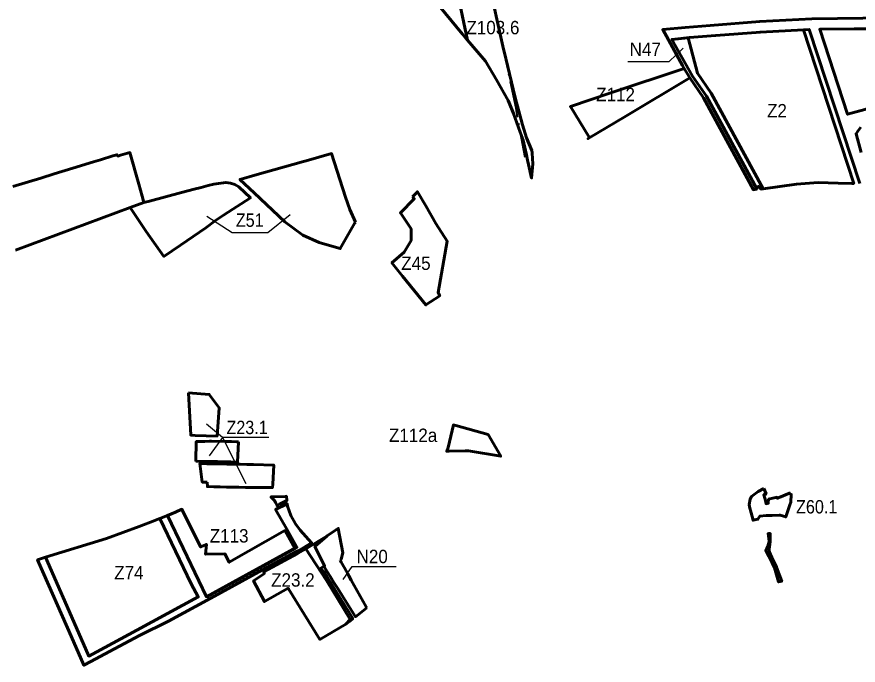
# Model space of a CAD drawing. Extents: x -650277 to -643420, y -1073980 to -1066720.
# Drawn here: x -648765 to -647259, y -1070690 to -1069529 of the extents above; entities that cross this region are included whole.
import ezdxf

# ---------------------------------------------------------------- set-up
doc = ezdxf.new("R2010")
doc.units = 0
doc.header["$LTSCALE"] = 9.6
doc.header["$PDMODE"] = 32
doc.header["$PDSIZE"] = 4.8
doc.linetypes.add('DOT_DASHED', pattern=[7.7, 5, -1.2, 0.3, -1.2])
for name, color, linetype, lineweight in [('1', 7, 'Continuous', 60), ('15', 7, 'Continuous', 60), ('17', 7, 'Continuous', 60), ('24', 7, 'Continuous', 60), ('3', 7, 'Continuous', 60), ('35', 7, 'Continuous', 60), ('36', 7, 'Continuous', 60), ('40', 7, 'Continuous', 60), ('42', 7, 'Continuous', 60), ('61', 7, 'Continuous', 60), ('62', 7, 'DOT_DASHED', 40), ('63', 7, 'Continuous', 25), ('7', 7, 'Continuous', 60), ('9', 7, 'Continuous', 60)]:
    doc.layers.add(name, color=color, linetype=linetype, lineweight=lineweight)

msp = doc.modelspace()

# ---------------------------------------------------------------- linework, layer by layer
at = {"layer": '1'}
for points in [[(-647356.899, -1069552.034), (-647433.779, -1069556.106), (-647433.779, -1069556.106), (-647513.66, -1069562.249), (-647514.067, -1069562.282), (-647560.836, -1069566.036), (-647563.104, -1069566.28)], [(-647369.3, -1069828.22), (-647330.46, -1069825.51), (-647294.38, -1069826.88), (-647270.09, -1069827.02), (-647266.581, -1069827.042), (-647356.899, -1069552.034)], [(-647563.104, -1069566.28), (-647546.777, -1069629.901), (-647521.943, -1069665.763)], [(-647521.943, -1069665.763), (-647428.993, -1069836.714), (-647369.3, -1069828.22)], [(-648368.25, -1070289.71), (-648372.1, -1070289.59), (-648380.97, -1070289.44), (-648392.94, -1070289.25), (-648416.93, -1070288.85), (-648420.39, -1070288.79), (-648428.98, -1070288.92), (-648435.93, -1070288.95), (-648444.15, -1070289.16), (-648444.85, -1070324.47)], [(-648444.85, -1070324.47), (-648444.85, -1070324.47), (-648430.02, -1070324.76), (-648418.1, -1070325), (-648406.09, -1070325.23), (-648394.08, -1070325.47), (-648382.06, -1070325.7), (-648370.07, -1070325.94), (-648368.25, -1070289.71)], [(-648307.13, -1070365.57), (-648305.47, -1070331.23), (-648341.46, -1070330.48), (-648353.32, -1070330.23), (-648365.35, -1070329.98), (-648389.43, -1070329.58), (-648401.41, -1070329.39), (-648413.45, -1070329.19), (-648425.43, -1070329), (-648437.65, -1070328.8), (-648433.46, -1070361.94), (-648424.31, -1070362.21)], [(-648424.31, -1070362.21), (-648424.05, -1070370), (-648412.75, -1070370.28), (-648401.35, -1070370.5), (-648390.06, -1070370.72), (-648378.73, -1070370.94), (-648367.67, -1070371.16), (-648355.67, -1070371.28), (-648343.67, -1070371.41), (-648331.67, -1070371.53), (-648319.67, -1070371.65), (-648307.67, -1070371.78), (-648307.13, -1070365.57)]]:
    msp.add_lwpolyline(points, dxfattribs=at)
for points in [[(-647251.002, -1069695.852), (-647219.628, -1069686.746), (-647203.374, -1069684.716), (-647139.649, -1069679.961), (-647113.255, -1069679.966), (-647082.761, -1069681.399), (-647083.356, -1069551.018), (-647140.247, -1069549.071), (-647158.572, -1069549.252), (-647211.05, -1069549.77), (-647227.623, -1069550.23), (-647327.682, -1069551.263), (-647277.71, -1069703.421)], [(-648458.28, -1070202.26), (-648454.038, -1070277.767), (-648446.18, -1070278.15), (-648406.8, -1070279.32), (-648403.04, -1070229.15), (-648420.7, -1070204.96)]]:
    msp.add_lwpolyline(points, close=True, dxfattribs=at)
at = {"layer": '15'}
for points in [[(-647204.293, -1069530.647), (-647341.697, -1069532.602), (-647434.969, -1069537.141), (-647523.931, -1069544.499), (-647568.792, -1069548.21), (-647608.81, -1069551.868), (-647598.735, -1069570.026), (-647573.15, -1069616.16), (-647570.37, -1069621.18), (-647560.36, -1069638.39), (-647535.588, -1069674.163), (-647446.322, -1069838.338), (-647441.19, -1069837.6), (-647440.46, -1069836.558), (-647530.471, -1069671.013), (-647555.266, -1069635.207), (-647592.199, -1069569.411), (-647560.836, -1069566.036), (-647514.067, -1069562.282), (-647513.66, -1069562.249), (-647433.779, -1069556.106), (-647433.779, -1069556.106), (-647356.899, -1069552.034), (-647346.554, -1069551.486), (-647256.034, -1069827.107)], [(-647256.061, -1069697.32), (-647277.71, -1069703.421), (-647327.682, -1069551.263), (-647204.208, -1069549.647)], [(-647253.45, -1069771.95), (-647262.46, -1069738.25), (-647259.11, -1069733.52), (-647253.97, -1069726.27)], [(-648213.87, -1070524.8), (-648221.359, -1070516.349), (-648215.48, -1070512.59), (-648214.34, -1070511.86), (-648231.53, -1070476.99), (-648210.48, -1070458.42), (-648247.67, -1070481.57), (-648211, -1070538)], [(-648176.54, -1070616.09), (-648169.28, -1070610.49), (-648163.8, -1070606.27), (-648213.87, -1070524.8)], [(-648211, -1070538), (-648168.575, -1070607.847), (-648176.54, -1070616.09)]]:
    msp.add_lwpolyline(points, dxfattribs=at)
for points in [[(-648303.705, -1070395.035), (-648302.028, -1070398.436), (-648299.32, -1070403.93), (-648295.18, -1070401.23), (-648281.907, -1070394.762), (-648282.582, -1070387.276), (-648284.37, -1070387.85), (-648310.275, -1070388.476)], [(-648550.72, -1070626.869), (-648636.757, -1070673.431), (-648655.178, -1070631.294), (-648714.161, -1070496.376), (-648728.255, -1070500.709), (-648725.835, -1070506.221), (-648668.207, -1070637.453), (-648645.331, -1070689.546), (-648632.652, -1070682.82), (-648599.66, -1070665.32), (-648545.76, -1070636.22), (-648494.04, -1070610.73), (-648417.855, -1070569.57), (-648325.21, -1070518.84), (-648264.56, -1070486.34), (-648260.57, -1070484.2), (-648237.475, -1070470.361), (-648257.96, -1070448.17), (-648266.416, -1070436.404), (-648274.808, -1070421.647), (-648280.974, -1070405.11), (-648281.388, -1070400.523), (-648302.01, -1070411.05), (-648282.01, -1070446.35), (-648263.859, -1070478.393), (-648425.835, -1070567.021), (-648439.409, -1070538.729), (-648495.666, -1070421.476), (-648509.227, -1070426.957), (-648452.97, -1070544.21), (-648440.531, -1070567.236)], [(-647404.96, -1070527.57), (-647401.35, -1070540.59), (-647395.75, -1070539.47), (-647404.879, -1070514.114), (-647413.552, -1070496.671), (-647417.297, -1070487.185), (-647418.038, -1070482.516), (-647417.482, -1070476.846), (-647416.37, -1070468.064), (-647416.148, -1070454.055), (-647418.49, -1070453.76), (-647420.13, -1070454.78), (-647420.22, -1070454.02), (-647418.41, -1070468.21), (-647420.74, -1070476.57), (-647422.285, -1070480.931), (-647424.226, -1070484.029), (-647422.19, -1070487.75), (-647414.6, -1070502.16), (-647410.86, -1070510.68), (-647408.82, -1070515.49)]]:
    msp.add_lwpolyline(points, close=True, dxfattribs=at)
msp.add_point((-648213.87, -1070524.8), dxfattribs=at)
at = {"layer": '17'}
msp.add_lwpolyline([(-647427.8, -1070373.32), (-647437.76, -1070378.66), (-647449.69, -1070387.83), (-647452.17, -1070392.38), (-647453.71, -1070401.81), (-647453.35, -1070406.09), (-647450.51, -1070416.96), (-647446.93, -1070429.99), (-647438.45, -1070428.47), (-647434.85, -1070422.64), (-647423.38, -1070421.87), (-647412.51, -1070421.5), (-647400.41, -1070421.08), (-647398.21, -1070421.15), (-647388.6, -1070424.24), (-647381.11, -1070402.45), (-647379.3, -1070397.57), (-647378.49, -1070383.91), (-647381.65, -1070381.45), (-647400.22, -1070389.64), (-647403.27, -1070390.91), (-647404, -1070388.84), (-647409.36, -1070390.24), (-647419.08, -1070392.52), (-647419.68, -1070399.59), (-647423.58, -1070400.59), (-647424.54, -1070394.78), (-647425.99, -1070390.47), (-647427.96, -1070384.64), (-647423.57, -1070382.64)], close=True, dxfattribs=at)
msp.add_lwpolyline([(-647427.8, -1070373.32), (-647437.76, -1070378.66), (-647449.69, -1070387.83), (-647452.17, -1070392.38), (-647453.71, -1070401.81), (-647453.35, -1070406.09), (-647450.51, -1070416.96), (-647446.93, -1070429.99), (-647438.45, -1070428.47), (-647434.85, -1070422.64), (-647423.38, -1070421.87), (-647412.51, -1070421.5), (-647400.41, -1070421.08), (-647398.21, -1070421.15), (-647388.6, -1070424.24), (-647381.11, -1070402.45), (-647379.3, -1070397.57), (-647378.49, -1070383.91), (-647381.65, -1070381.45), (-647400.22, -1070389.64), (-647403.27, -1070390.91), (-647404, -1070388.84), (-647409.36, -1070390.24), (-647419.08, -1070392.52), (-647419.68, -1070399.59), (-647423.58, -1070400.59), (-647424.54, -1070394.78), (-647425.99, -1070390.47), (-647427.96, -1070384.64), (-647423.57, -1070382.64)], close=True, dxfattribs=at)
at = {"layer": '24'}
msp.add_lwpolyline([(-648495.666, -1070421.476), (-648439.409, -1070538.729), (-648425.835, -1070567.021), (-648267.801, -1070480.55), (-648285.75, -1070448.49), (-648385.085, -1070505.351), (-648393.14, -1070490.07), (-648427.41, -1070491.08), (-648426.05, -1070473.34), (-648436.22, -1070478.01), (-648469.77, -1070410.47), (-648481.18, -1070415.62)], close=True, dxfattribs=at)
at = {"layer": '3'}
msp.add_lwpolyline([(-648767.83, -1069946.87), (-648562.242, -1069870.301), (-648537.86, -1069861.22), (-648541.06, -1069849.78), (-648546.97, -1069828.68), (-648562.87, -1069771.85), (-648579.63, -1069776.66), (-648584.65, -1069778.1), (-648586.09, -1069775.75), (-648593.59, -1069778.06), (-648615.88, -1069784.93), (-648627.99, -1069788.67), (-648665.05, -1069799.99), (-648698.31, -1069810.16), (-648722.24, -1069817.54), (-648772.48, -1069832.83)], dxfattribs=at)
for points in [[(-648159.1, -1069896.39), (-648169.15, -1069873.81), (-648176.78, -1069851.74), (-648201.83, -1069773.86), (-648247.27, -1069786.64), (-648251.94, -1069787.95), (-648339.05, -1069812.45), (-648363.68, -1069819.31), (-648365.81, -1069819.9), (-648340.38, -1069843.78), (-648285.62, -1069895.71), (-648253.13, -1069919.7), (-648223.99, -1069932.96), (-648218.245, -1069934.595), (-648186.268, -1069943.697), (-648160.04, -1069897.73)], [(-648470.79, -1069843.51), (-648528.11, -1069858.73), (-648537.86, -1069861.22), (-648562.242, -1069870.301), (-648533.79, -1069913.49), (-648502.048, -1069957.969), (-648472.6, -1069937.81), (-648426.82, -1069906.88), (-648409.44, -1069893.25), (-648396.87, -1069885.43), (-648395.03, -1069884.22), (-648347.06, -1069853), (-648367.64, -1069833.35), (-648374.89, -1069829.22), (-648382.8, -1069826.55), (-648391.08, -1069825.45), (-648408.45, -1069827.83), (-648412.74, -1069828.72), (-648422.75, -1069830.78), (-648435.53, -1069834.44), (-648447.98, -1069837.44)], [(-648057.11, -1069851.12), (-648053.61, -1069854.64), (-648078.54, -1069880.01), (-648059.32, -1069908.27), (-648059.5, -1069929.52), (-648071.58, -1069950.39), (-648093.67, -1069969.42), (-648074.96, -1069993.46), (-648032.85, -1070044.73), (-648008.18, -1070028.25), (-648010.44, -1070023.66), (-648010.94, -1070022.65), (-647994.71, -1069930.53), (-648015.11, -1069898.98), (-648032.94, -1069867.46), (-648048.08, -1069841.95)]]:
    msp.add_lwpolyline(points, close=True, dxfattribs=at)
at = {"layer": '35'}
msp.add_lwpolyline([(-647740.74, -1069744.24), (-647742.36, -1069746.93), (-647674.901, -1069706.701), (-647560.36, -1069638.39), (-647570.37, -1069621.18), (-647701.61, -1069665.279), (-647774.11, -1069689.64)], close=True, dxfattribs=at)
at = {"layer": '36'}
for points in [[(-647962.82, -1070305.9), (-647956.36, -1070305.77), (-647898.82, -1070315.51), (-647921.51, -1070276.76), (-647979.24, -1070260.71), (-647983.6, -1070259.5), (-647992.71, -1070300.01), (-647995.46, -1070306.55), (-647991.12, -1070306.46)], [(-648636.757, -1070673.431), (-648550.72, -1070626.869), (-648440.531, -1070567.236), (-648452.97, -1070544.21), (-648509.227, -1070426.957), (-648526.28, -1070433.85), (-648538.611, -1070438.388), (-648546.377, -1070441.246), (-648604.92, -1070462.79), (-648714.161, -1070496.376), (-648655.178, -1070631.294)], [(-648636.757, -1070673.431), (-648550.72, -1070626.869), (-648440.531, -1070567.236), (-648452.97, -1070544.21), (-648509.227, -1070426.957), (-648526.28, -1070433.85), (-648538.611, -1070438.388), (-648546.377, -1070441.246), (-648604.92, -1070462.79), (-648714.161, -1070496.376), (-648655.178, -1070631.294)]]:
    msp.add_lwpolyline(points, close=True, dxfattribs=at)
at = {"layer": '40'}
msp.add_line((-648214.34, -1070511.86), (-648215.48, -1070512.59), dxfattribs=at)
for points in [[(-648186.441, -1070501.65), (-648186.088, -1070501.313), (-648184.791, -1070500.073), (-648181.386, -1070488.724), (-648189.93, -1070444.71), (-648194.56, -1070447.8), (-648194.56, -1070447.799), (-648209.82, -1070457.98), (-648210.48, -1070458.42), (-648231.53, -1070476.99), (-648214.34, -1070511.86)], [(-648166.63, -1070537.28), (-648170.72, -1070529.92), (-648172.96, -1070525.9), (-648178.7, -1070515.58), (-648184.54, -1070505.07), (-648186.441, -1070501.65)], [(-648215.48, -1070512.59), (-648210.19, -1070521.07), (-648203.83, -1070531.25), (-648197.59, -1070541.27), (-648190.71, -1070552.3), (-648182.98, -1070564.68), (-648171.02, -1070583.86), (-648159.23, -1070602.75), (-648138.93, -1070587.1)], [(-648138.93, -1070587.1), (-648140.05, -1070585.09), (-648166.63, -1070537.28)]]:
    msp.add_lwpolyline(points, dxfattribs=at)
at = {"layer": '42'}
msp.add_lwpolyline([(-647555.266, -1069635.207), (-647530.471, -1069671.013), (-647440.46, -1069836.558), (-647437.46, -1069832.27), (-647433.32, -1069837.33), (-647428.993, -1069836.714), (-647521.943, -1069665.763), (-647546.777, -1069629.901), (-647563.104, -1069566.28), (-647592.199, -1069569.411)], close=True, dxfattribs=at)
at = {"layer": '61'}
for points in [[(-648034.421, -1069167.61), (-648034.421, -1069167.61), (-648033, -1069189), (-648015, -1069300), (-648010.092, -1069322.087), (-647980.331, -1069465.915), (-647958.34, -1069570.699), (-647925.99, -1069608.57), (-647906.16, -1069641.48), (-647885.665, -1069678.788), (-647885.663, -1069678.794), (-647883.51, -1069682.71), (-647875.82, -1069701.85), (-647875.82, -1069701.85), (-647864.19, -1069735.12), (-647858.44, -1069749.43), (-647852.63, -1069775.7), (-647850.66, -1069785.74), (-647849.165, -1069793.367)], [(-647852.78, -1069745.71), (-647859.722, -1069722.428), (-647872.87, -1069673.56), (-647892.79, -1069591.06), (-647892.789, -1069591.06), (-647893.75, -1069587.08), (-647922.04, -1069459.71), (-647925.16, -1069445.68), (-647928.41, -1069431.03), (-647945.28, -1069355.1), (-647956.27, -1069311.58), (-647962.2, -1069290.88)], [(-647841.402, -1069792.351), (-647842.489, -1069773.282), (-647842.622, -1069770.956), (-647843.337, -1069769.013), (-647843.443, -1069768.293), (-647852.78, -1069745.71)], [(-647849.165, -1069793.367), (-647843.74, -1069817.63), (-647841.402, -1069792.351)]]:
    msp.add_lwpolyline(points, dxfattribs=at)
at = {"layer": '62'}
msp.add_lwpolyline([(-647855.282, -1069780.988), (-647871.488, -1069692.474), (-647887.497, -1069616.134), (-647904.75, -1069533.925), (-647921.593, -1069453.674)], dxfattribs=at)
at = {"layer": '63'}
for q in [(-648421, -1070315), (-648355.27, -1070364.25)]:
    msp.add_line((-648397, -1070282), q, dxfattribs=at)
for points in [[(-647671, -1069609), (-647597, -1069609), (-647572, -1069585)], [(-648425, -1069886), (-648380, -1069915), (-648316, -1069915), (-648276, -1069883)], [(-648314, -1070282), (-648397, -1070282), (-648426, -1070258)], [(-648181, -1070536), (-648165, -1070513), (-648086, -1070513)]]:
    msp.add_lwpolyline(points, dxfattribs=at)
at = {"layer": '7'}
msp.add_lwpolyline([(-648247.67, -1070481.57), (-648262.69, -1070489.67), (-648323.59, -1070522.48), (-648322.18, -1070525.44), (-648341.41, -1070538.42), (-648322.16, -1070575.76), (-648289.22, -1070557.15), (-648279.736, -1070551.783), (-648278.89, -1070553.14), (-648222.58, -1070643.48), (-648176.54, -1070616.09), (-648168.575, -1070607.847), (-648211, -1070538)], close=True, dxfattribs=at)
at = {"layer": '9'}
msp.add_lwpolyline([(-648015, -1069300), (-648033, -1069189), (-648034.421, -1069167.61), (-648071.9, -1069142.06), (-648073.66, -1069140.86), (-648141.92, -1069121.66), (-648171.14, -1069122.83), (-648207.77, -1069129.95), (-648209.89, -1069130.36), (-648226.51, -1069136.57), (-648248.14, -1069144.65), (-648268.87, -1069158.61), (-648270.92, -1069159.99), (-648275.19, -1069162.87), (-648280.1, -1069166.97), (-648203.01, -1069264.73), (-648127.77, -1069361.38), (-648068.71, -1069436.57), (-647967.53, -1069559.94), (-647958.214, -1069571.3), (-647980.331, -1069465.915), (-648010.092, -1069322.087)], close=True, dxfattribs=at)

# ---------------------------------------------------------------- texts
at = {"layer": '63'}
for s, width, p in [('Z103.6', 0.95, (-647960.304, -1069560.198)), ('N47', 0.95, (-647668, -1069599)), ('Z112', 0.95, (-647728, -1069680)), ('Z2', 0.95, (-647422, -1069709)), ('Z51', 0.9, (-648373.214, -1069904.865)), ('Z45', 0.95, (-648077, -1069982)), ('Z23.1', 0.9, (-648390, -1070276)), ('Z112a', 0.95, (-648099, -1070290)), ('Z60.1', 0.9, (-647370, -1070418)), ('Z113', 0.95, (-648420, -1070470)), ('N20', 0.95, (-648157, -1070507)), ('Z74', 0.95, (-648591, -1070536)), ('Z23.2', 0.95, (-648310, -1070549))]:
    msp.add_text(s, height=24, dxfattribs=dict(at, width=width)).set_placement(p)

doc.saveas('drawing.dxf')
